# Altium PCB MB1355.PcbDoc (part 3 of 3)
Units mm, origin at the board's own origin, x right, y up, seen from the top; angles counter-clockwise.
Board outline 70.13 x 64.58 mm, 4 copper layers (L1, L2, L3, L4), stack 1.565 mm thick; 206 components, 160 nets, 707 pads, 1364 vias.
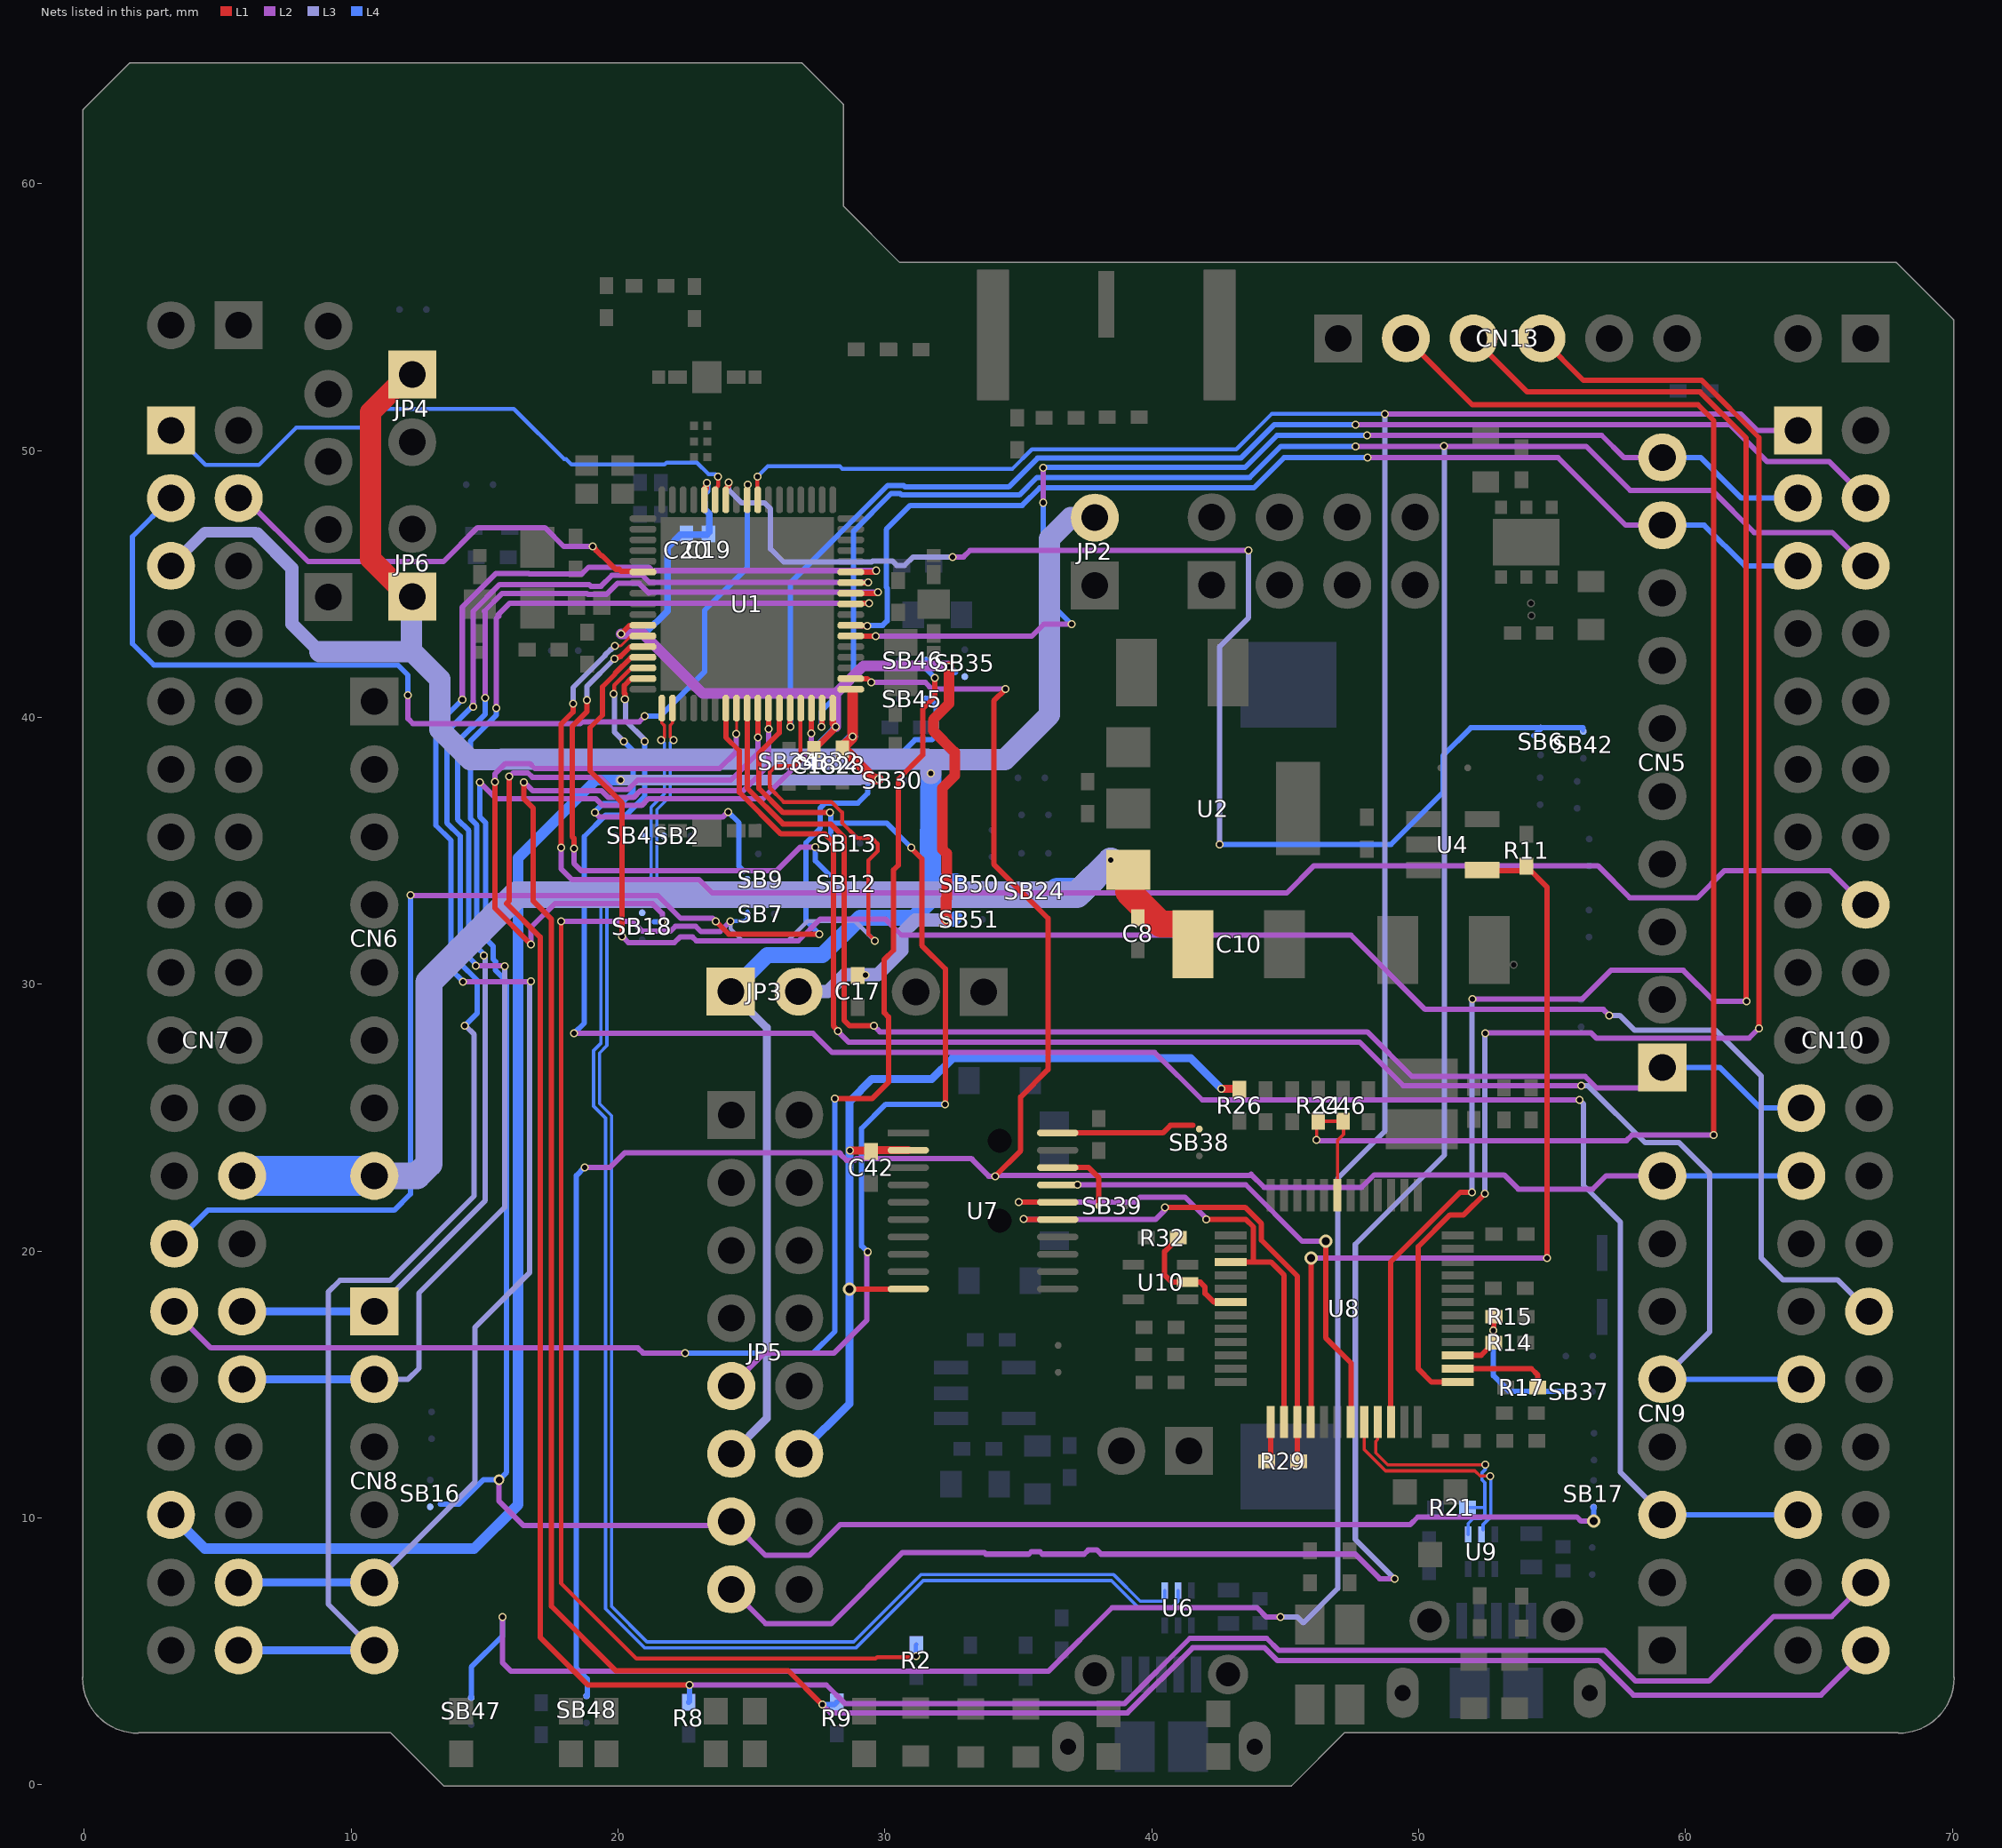
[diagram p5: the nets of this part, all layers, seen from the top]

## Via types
v1: diameter 0.3, hole 0.2, L1 to L4, tented both sides, 662 vias
v2: diameter 0.403, hole 0.2, L1 to L4, tented both sides, 628 vias
v3: diameter 0.4, hole 0.25, L1 to L4, tented both sides, 50 vias
v4: diameter 0.5, hole 0.3, L1 to L4, tented both sides, 24 vias

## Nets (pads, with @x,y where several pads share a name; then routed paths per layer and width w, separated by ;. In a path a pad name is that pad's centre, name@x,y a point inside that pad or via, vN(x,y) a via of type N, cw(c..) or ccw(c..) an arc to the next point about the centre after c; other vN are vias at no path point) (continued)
PB3: JP5.9 SB13.1 U1.63 | length 37.9
  L1 w0.2: U1.63@26.044,40.349 26.044,39.42 25.278,38.654 25.278,37.342 26.187,36.433 v1(27.939,36.434) ; v1(30.989,35.124) 30.989,35.104 31.385,34.708 31.385,31.456 32.263,30.578 32.263,25.522 v1(32.249,25.508)
  L2 w0.2: JP5.9@24.247,14.947 25.485,16.185 28.096,16.185 29.329,17.418 29.329,19.965 v1(29.36,19.965)
  L4 w0.2: v1(27.939,36.434) 27.939,36.421 27.97,36.39 27.97,36.043 ; 27.97,35.398 27.97,36.043 ; v1(29.36,19.965) 29.128,20.197 29.128,24.6 30.036,25.508 v1(32.249,25.508) ; v1(30.989,35.124) 30.07,36.043 27.97,36.043
PB4: CN10.4 U1.64 | length 50.1
  L1 w0.2: U1.64@26.444,40.349 26.444,39.658 v1(26.459,39.643)
  L2 w0.2: v1(47.628,50.968) 61.673,50.968 63.054,49.586 65.384,49.586 CN10.4@66.75,48.22
  L4 w0.2: v1(26.459,39.643) 26.459,45.033 26.453,45.039 30.103,48.689 30.702,48.689 30.756,48.636 34.637,48.636 35.719,49.718 43.338,49.718 44.593,50.973 44.598,50.968 v1(47.628,50.968)
PB5: R2.1 SB7.1 U1.65 | length 67
  L1 w0.15: v1(17.87,32.352) 17.87,7.544 20.687,4.727 29.644,4.727 29.707,4.79 31.168,4.79 v1(31.168,4.829) ; U1.65@26.844,40.349 26.838,40.343 26.838,38.372 26.736,38.269 26.725,38.269 26.625,38.17 25.901,38.17 25.685,37.954 25.685,37.36 26.209,36.836 27.996,36.836 28.392,36.44 28.392,36.053 28.968,35.477 29.512,35.477 29.63,35.36 29.63,35.358 29.729,35.259 29.729,34.989 29.389,34.649 29.389,31.876 v1(29.63,31.634)
  L2 w0.2: v1(17.87,32.352) 20.536,32.352 20.903,31.985 21.963,31.985 22.155,32.177 22.906,32.177 23.108,31.975 23.825,31.975 v1(24.214,32.364)
  L3 w0.15: v1(24.214,32.364) 24.214,32.086 24.664,31.636 26.37,31.636 27.098,32.365 28.886,32.365 29.63,31.62 v1(29.63,31.634)
  L4 w0.15: v1(17.87,32.352) v1@17.872,32.354 ; v1@24.214,32.384 v1(24.214,32.364) 24.737,32.364 24.847,32.474 SB7.1@24.847,32.739 ; v1(31.168,4.829) 31.168,5.256 R2.1@31.175,5.263
PB6: JP5.13 SB16.2 SB17.1 U1.66 | length 88.4
  L1 w0.2: v1(27.238,39.405) 27.238,40.343 U1.66@27.244,40.349
  L2 w0.2: v1(14.816,37.576) 15.436,36.956 19.165,36.956 19.424,36.697 20.885,36.697 21.144,36.956 25.439,36.956 27.244,38.761 27.238,38.767 v1(27.238,39.405) 27.238,39.451 v1@27.23,39.459 ; v3(15.546,11.427) 15.546,10.632 16.452,9.726 24.399,9.726 25.529,8.596 27.166,8.596 28.327,9.757 49.69,9.757 49.967,10.034 55.933,10.034 56.089,9.878 v4(56.556,9.878)
  L4 w0.2: 13.35,10.515 14.04,10.515 14.952,11.427 v3(15.546,11.427) ; v1(14.816,37.576) 14.816,36.285 15.048,36.053 15.048,31.7 15.326,31.422 15.326,31.228 15.326,30.937 15.421,30.842 15.401,30.822 15.401,30.532 15.825,30.108 15.825,11.71 v3@15.544,11.429 ; v4(56.556,9.878) SB17.1@56.556,10.405
PB7: CN10.6 JP5.15 U1.67 | length 121.2
  L1 w0.2: v1(27.621,39.652) 27.644,39.675 U1.67@27.644,40.349
  L2 w0.2: JP5.15@24.247,7.327 25.535,6.039 27.995,6.039 30.653,8.697 33.74,8.697 33.792,8.645 35.391,8.645 35.481,8.736 35.813,8.736 35.903,8.645 37.463,8.645 37.618,8.8 37.949,8.8 38.104,8.645 47.623,8.645 48.539,7.729 v1(49.095,7.729) ; v1(47.635,50.159) 56.275,50.159 57.923,48.511 60.99,48.511 62.569,46.932 65.498,46.932 CN10.6@66.75,45.68
  L3 w0.2: v1(49.095,7.729) 47.627,9.197 47.627,20.257 50.965,23.595 50.965,50.166 v1(50.955,50.176)
  L4 w0.2: v1(27.621,39.652) 27.621,40.234 28.826,41.439 28.826,46.98 30.235,48.389 30.578,48.389 30.631,48.336 35.039,48.336 35.692,48.989 43.667,48.989 44.837,50.159 v1(47.635,50.159)
PB8: CN5.10 CN10.3 U1.6 | length 44.5
  L1 w0.2: U1.6@28.722,43.052 29.657,43.052 v1(29.663,43.046)
  L2 w0.2: v1(29.663,43.046) 35.506,43.046 35.956,43.496 v1(36.992,43.496) ; v1@35.925,49.364 35.925,48.095 35.93,48.09 v1(35.93,48.049) ; v1(48.062,50.564) 56.851,50.564 56.857,50.57 57.683,49.744 CN5.10@59.13,49.744
  L4 w0.2: v1@35.925,49.368 43.491,49.368 44.693,50.57 44.699,50.564 v1(48.062,50.564) ; v1(35.93,48.049) 35.93,44.558 v1(36.992,43.496) ; CN5.10@59.13,49.744 60.565,49.744 62.089,48.22 CN10.3@64.21,48.22
  other v1: 35.927,49.36
PB9: CN5.9 CN10.5 U1.7 | length 41.9
  L1 w0.2: U1.7@28.722,43.452 28.728,43.458 28.749,43.437 v1(29.34,43.437)
  L2 w0.2: v1(48.077,49.74) 55.222,49.74 57.758,47.204 CN5.9@59.13,47.204
  L4 w0.2: v1(29.34,43.437) 29.35,43.448 29.919,43.448 30.087,43.616 30.087,44.842 30.048,44.881 30.048,47.047 30.949,47.948 35.146,47.948 35.803,48.605 43.825,48.605 44.96,49.74 v1(48.077,49.74) ; CN5.9@59.13,47.204 60.696,47.204 62.22,45.68 CN10.5@64.21,45.68
PB10: SB6.2 SB42.1 U1.28 | length 51.1
  L1 w0.2: U1.28@24.044,48.155 24.044,48.573 24.119,48.648 v1@24.119,48.676 ; v1(24.152,48.809) 24.152,48.715 24.155,48.712 v1@24.135,48.692 ; v1@24.119,48.676 24.119,48.692 v1@24.135,48.692 ; v1@24.119,48.676 v1@24.135,48.692
  L2 w0.2: v1(32.543,46.016) 32.948,46.016 33.184,46.252 v1(43.628,46.252)
  L3 w0.2: v1(24.152,48.809) 24.152,48.522 24.627,48.047 25.485,48.047 25.716,47.817 25.716,46.314 26.209,45.82 29.502,45.82 29.534,45.852 30.291,45.852 30.447,45.696 30.737,45.696 31.057,46.016 v1(32.543,46.016) ; v1(42.546,35.247) 42.546,42.659 43.628,43.741 v1(43.628,46.252)
  L4 w0.127: SB6.2@54.57,39.602 54.578,39.61 SB6.2@54.58,39.612 ; SB42.1@56.155,39.496 56.155,39.612
  L4 w0.2: v1(42.546,35.247) 48.968,35.247 50.907,37.186 50.907,38.567 51.95,39.61 54.578,39.61 54.606,39.61 54.314,39.318 ; SB6.2@54.58,39.612 56.155,39.612
PB11: CN7.1 U1.29 | length 23.4
  L1 w0.15: 23.717,48.654 23.752,48.689 v1(23.752,49.024)
  L4 w0.15: CN7.1@3.25,50.76 4.544,49.466 6.548,49.466 7.938,50.856 10.412,50.856 11.117,51.561 16.1,51.561 17.985,49.676 18.055,49.676 18.255,49.476 21.746,49.476 21.822,49.552 22.96,49.552 23.39,49.122 23.654,49.122 v1(23.752,49.024) 23.752,49.014 v1@23.733,48.995
PB12: CN10.16 U1.46 | length 61.5
  L1 w0.1: v1(19.88,42.678) 20.106,42.678 20.48,43.052 U1.46@20.941,43.052
  L1 w0.2: v1(17.87,35.119) 17.87,39.757 18.32,40.207 v1(18.32,40.516)
  L2 w0.2: v1@17.877,35.102 17.877,34.316 18.262,33.931 23.025,33.931 23.536,33.42 45.055,33.42 46.077,34.442 56.713,34.442 57.912,33.243 60.441,33.243 61.459,34.261 65.398,34.261 66.679,32.98 CN10.16@66.75,32.98
  L3 w0.2: v1(18.32,40.516) 18.32,41.118 19.516,42.314 19.516,42.341 19.721,42.546 19.748,42.546 v1(19.88,42.678)
PB13: SB12.1 U1.47 | length 21
  L1 w0.1: 20.076,42.29 20.032,42.315 20.468,42.682 U1.47@20.468,42.652
  L1 w0.2: v1(18.346,35.096) 18.346,35.47 18.282,35.534 18.282,39.66 18.831,40.209 v1(18.831,40.643) ; v1(19.866,42.196) 20.097,42.281 20.468,42.652 U1.47@20.941,42.652
  L2 w0.2: v1(18.346,35.096) 18.346,34.535 18.617,34.264 25.952,34.264 26.821,35.133 v1(27.391,35.133)
  L3 w0.2: v1(18.831,40.643) 18.831,41.161 v1(19.866,42.196)
  L4 w0.2: v1(27.391,35.133) 27.391,34.629 27.912,34.108
PB14: CN10.28 U1.48 | length 69.4
  L1 w0.15: U1.48@20.483,42.252 U1.48@20.941,42.252
  L1 w0.17: 19.418,41.15 19.897,41.629 19.897,41.657
  L1 w0.2: 19.418,41.15 19.418,40.085 18.952,39.619 18.952,37.999 20.154,36.797 v1(20.154,31.796) ; 19.897,41.657 U1.48@20.483,42.242
  L2 w0.2: v1(20.154,31.796) 20.389,31.561 22.112,31.561 22.324,31.773 22.791,31.773 22.938,31.626 26.761,31.626 27.583,32.448 30.017,32.448 30.622,31.843 47.463,31.843 50.247,29.059 56.92,29.059 v1(57.148,28.831)
  L3 w0.2: v1(57.148,28.831) 57.155,28.838 57.53,28.838 58.084,28.284 61.113,28.284 62.827,26.57 62.827,19.746 63.644,18.929 65.688,18.929 CN10.28@66.877,17.74
PB15: SB9.1 U1.49 | length 15.1
  L1 w0.15: v1@19.863,40.906 19.863,41.208 20.507,41.852 U1.49@20.941,41.852
  L2 w0.2: v1(19.138,36.44) 19.313,36.265 23.925,36.265 24.151,36.491 24.151,36.484 v1(24.126,36.459)
  L3 w0.2: v1@19.863,40.906 19.863,39.453 v1(20.21,39.106)
  L4 w0.2: v1(19.138,36.44) 19.132,36.446 19.132,36.458 19.447,36.773 20.132,36.773 20.569,37.21 20.569,38.747 v1(20.21,39.106) ; v1(24.126,36.459) 24.531,36.054 24.531,34.422 24.72,34.233
  other v1: 19.836,40.884
PC0: CN7.28 CN8.1 U1.9 | length 48.3
  L1 w0.2: U1.9@28.722,44.252 28.804,44.252 28.823,44.271 v1(29.407,44.271)
  L2 w0.2: v1(15.432,40.352) 15.432,43.699 15.536,43.802 15.499,43.839 15.931,44.271 v1(29.407,44.271)
  L3 w0.2: CN8.1@10.87,17.74 15.029,21.899 15.029,31.072 15.019,31.082 v1(14.976,31.082)
  L4 w0.2: v1(14.976,31.082) 15.023,31.082 14.714,31.391 14.714,35.963 14.466,36.211 14.466,39.112 15.432,40.078 v1(15.432,40.352)
  L4 w0.3: CN7.28@5.917,17.74 CN8.1@10.87,17.74
PC1: CN7.30 CN8.2 U1.10 | length 54.7
  L1 w0.2: U1.10@28.722,44.652 29.692,44.652 v1(29.737,44.697)
  L2 w0.2: v1(14.679,30.69) 15.738,30.69 v1(15.751,30.677) ; v1(15.016,40.734) 15.016,43.955 14.991,43.98 15.652,44.641 18.838,44.641 18.862,44.616 19.576,44.616 19.98,45.02 20.793,45.02 21.157,44.656 21.199,44.697 v1(29.737,44.697)
  L3 w0.2: CN8.2@10.87,15.2 12.134,15.2 12.542,15.608 12.542,18.429 15.751,21.638 v1(15.751,30.677)
  L4 w0.2: v1(14.679,30.69) 14.679,30.744 14.414,31.009 14.414,35.758 13.988,36.184 13.988,39.087 15.016,40.115 v1(15.016,40.734)
  L4 w0.3: CN7.30@5.917,15.2 CN8.2@10.87,15.2
PC2: CN7.38 CN8.6 U1.11 | length 65.6
  L1 w0.2: U1.11@28.722,45.052 v1@29.365,45.052
  L2 w0.2: v1(14.566,40.398) 14.566,43.979 15.571,44.983 18.919,44.983 18.987,44.916 19.364,44.916 19.767,45.32 20.918,45.32 21.182,45.056 23.417,45.056 ; 23.417,45.056 24.204,45.056 24.211,45.063 v1(29.365,45.063)
  L3 w0.2: CN8.6@10.87,5.04 9.139,6.771 9.139,18.467 9.578,18.906 11.448,18.906 14.613,22.071 14.613,28.116 v1@14.275,28.454
  L4 w0.2: v1(14.263,28.454) 14.73,28.921 14.73,30.144 14.084,30.79 14.084,35.557 13.589,36.052 13.589,39.458 v1@14.516,40.385 ; v1(14.566,40.398) 14.566,40.599
  L4 w0.3: CN7.38@5.79,5.04 CN8.6@10.87,5.04
PC3: CN7.36 CN8.5 U1.12 | length 64.7
  L1 w0.2: U1.12@28.722,45.452 29.618,45.452 v1@29.668,45.502
  L2 w0.2: v1(14.166,40.667) 14.166,44.134 15.421,45.389 16.658,45.389 16.672,45.376 18.644,45.376 18.901,45.632 21.152,45.632 21.33,45.454 21.379,45.502 v1(29.679,45.502) ; v1(14.194,30.103) 16.722,30.103 v1(16.733,30.114)
  L3 w0.2: CN8.5@10.87,7.58 14.637,11.347 14.637,17.14 16.681,19.184 16.681,30.062 v1(16.733,30.114)
  L4 w0.2: v1(14.166,40.667) 13.177,39.678 13.177,35.955 13.741,35.391 13.741,30.556 v1(14.194,30.103)
  L4 w0.3: CN7.36@5.79,7.58 CN8.5@10.87,7.58
PC4: CN10.1 SB47.2 U1.25 | length 124.3
  L1 w0.15: U1.25@25.21,48.189 25.21,48.557 25.226,48.557 25.226,48.996 v1@25.21,49.012
  L2 w0.2: v1(15.668,6.291) 15.668,4.578 15.983,4.263 36.136,4.263 38.511,6.638 43.944,6.638 44.294,6.288 v1(44.814,6.288) ; v1(48.729,51.363) 62.076,51.363 62.679,50.76 CN10.1@64.21,50.76
  L3 w0.2: v1(44.814,6.288) 45.457,6.288 45.679,6.066 46.971,7.358 46.971,22.728 48.727,24.484 48.727,51.361 v1(48.729,51.363)
  L4 w0.15: v1@25.21,49.012 25.611,49.413 28.308,49.413 28.4,49.321 34.781,49.321 35.509,50.049 43.168,50.049 44.49,51.371 48.721,51.371 v1(48.729,51.363)
  L4 w0.2: SB47.2@14.505,3.267 14.505,4.411 15.668,5.574 v1(15.668,6.291)
  other v1: 25.225,49.026
PC5: CN7.3 U1.26 | length 38.2
  L2 w0.2: v1(12.131,40.827) 12.131,39.954 12.311,39.774 18.592,39.774 18.659,39.842 20.802,39.842 v1(21.006,40.046)
  L4 w0.2: CN7.3@3.25,48.22 1.807,46.777 1.807,42.763 2.607,41.963 11.751,41.963 12.131,41.583 v1(12.131,40.827) ; v1(21.006,40.046) 21.574,40.046 23.24,41.712 23.24,44.012 24.851,45.623 v1@24.851,48.728
  other v1: 24.856,48.719
PC6: CN9.3 CN10.33 U1.50 | length 76.3
  L1 w0.2: v1@20.277,40.704 20.265,40.736 20.265,40.882 20.241,40.907 20.241,41.197 20.496,41.452 U1.50@20.941,41.452
  L2 w0.2: v1(18.349,28.159) 27.31,28.159 28.024,27.445 40.112,27.445 41.891,25.666 v1(56.027,25.666)
  L3 w0.2: v1@20.277,40.704 20.277,39.883 21.002,39.158 v1(21.002,39.106) ; v1(56.027,25.666) 56.174,25.519 56.174,22.47 57.563,21.081 57.563,11.711 59.13,10.144 CN9.3@59.13,10.12
  L4 w0.2: v1(18.349,28.159) 18.735,28.545 18.735,35.54 19.527,36.332 20.293,36.332 21.002,37.041 v1(21.002,39.106) ; CN9.3@59.13,10.12 CN10.33@64.21,10.12
  other v1: 20.259,40.68
PC10: CN9.5 CN10.29 U1.58 | length 63.3
  L1 w0.2: U1.58@24.044,40.349 24.044,39.253 24.544,38.753 24.544,37.195 26.103,35.636 27.752,35.636 28.067,35.321 28.067,28.44 v1@28.252,28.255
  L2 w0.2: v1(28.248,28.255) 28.248,28.222 28.637,27.833 47.785,27.833 49.42,26.198 v1(56.096,26.196)
  L3 w0.2: v1(56.096,26.196) 56.355,26.196 58.488,24.063 59.762,24.063 60.9,22.925 60.9,16.97 CN9.5@59.13,15.2
  L4 w0.2: CN9.5@59.13,15.2 CN10.29@64.337,15.2
PC11: SB18.2 U1.59 | length 24.9
  L1 w0.1: v1(24.435,39.387) 24.444,39.396 U1.59@24.444,40.349
  L1 w0.2: v1(15.389,37.592) 15.389,32.852 16.733,31.508 v1(16.733,31.489)
  L2 w0.2: v1(15.389,37.592) 15.385,37.596 15.385,37.88 15.779,38.274 16.698,38.274 16.886,38.086 23.805,38.086 24.435,38.716 v1(24.435,39.387) ; v1(16.733,31.489) 16.733,32.124 17.631,33.022 21.292,33.022 21.658,32.656 21.658,32.335 v1(21.653,32.335)
  L4 w0.2: 21.351,32.348 21.364,32.335 v1(21.653,32.335)
PC12: CN5.1 CN10.21 U1.60 | length 52.1
  L1 w0.2: U1.60@24.844,40.349 24.844,37.346 26.183,36.007 27.973,36.007 28.472,35.508 28.472,28.652 28.68,28.444 v1(29.591,28.444)
  L2 w0.2: v1(29.591,28.444) 29.813,28.222 48.075,28.222 49.751,26.546 56.241,26.546 56.674,26.113 58.359,26.113 CN5.1@59.13,26.884
  L4 w0.2: CN5.1@59.13,26.884 61.28,26.884 62.804,25.36 CN10.21@64.337,25.36
PC13: CN9.8 CN10.23 SB48.2 U1.2 | length 93.3
  L1 w0.2: U1.2@28.722,41.452 29.34,41.452 v1(29.483,41.309) ; v1(34.136,22.812) 35.086,23.762 35.086,25.78 36.109,26.803 36.109,32.475 34.08,34.504 34.08,40.619 v1(34.524,41.063)
  L2 w0.2: v1(18.75,23.139) 19.706,23.139 20.247,23.68 28.304,23.68 28.336,23.648 28.336,23.631 28.564,23.403 28.854,23.403 28.928,23.477 33.239,23.477 33.287,23.429 33.287,23.414 33.89,22.812 v1(34.136,22.812) 34.16,22.836 43.677,22.836 43.721,22.88 44.212,22.389 47.865,22.389 48.335,22.859 53.201,22.859 53.733,22.327 56.525,22.327 57.018,22.82 CN9.8@59.13,22.82 ; v1(29.483,41.309) 31.52,41.309 31.766,41.063 v1(34.524,41.063)
  L4 w0.2: v1(18.75,23.139) 18.442,22.832 18.442,4.376 18.845,3.973 18.845,3.355 SB48.2@18.821,3.331 ; CN9.8@59.13,22.82 CN10.23@64.337,22.82
PC14: CN7.25 SB45.2 | length 49.7
  L1 w0.2: v1(23.664,32.363) 24.145,31.882 v1(27.54,31.882) v1@27.571,31.882
  L2 w0.2: v1(12.226,33.339) 12.243,33.322 21.499,33.322 22.344,32.477 23.55,32.477 v1(23.664,32.363)
  L4 w0.2: CN7.25@3.377,20.28 4.631,21.534 11.614,21.534 12.226,22.145 v1(12.226,33.339) ; v1(27.54,31.882) 27.041,32.381 27.041,35.306 27.583,35.848 27.583,36.608 27.764,36.789 28.985,36.789 29.351,37.155 29.351,38.25 29.593,38.492 30.459,38.492 31.129,39.162 31.767,39.162 31.913,39.308 31.913,40.483 31.698,40.698 SB45.2@31.533,40.698
PC15: CN7.27 SB46.2 | length 53.5
  L1 w0.2: v1(28.123,25.72) 29.528,25.72 30.136,26.328 30.136,28.778 29.977,28.937 29.977,30.932 30.324,31.278 30.324,34.282 30.504,34.463 30.504,37.686 31.413,38.595 31.413,40.088 31.416,40.091 31.416,40.323 31.872,40.779 v1(31.872,41.484)
  L2 w0.2: CN7.27@3.377,17.74 4.744,16.373 20.744,16.373 20.936,16.181 v1(22.516,16.181)
  L4 w0.2: v1(22.516,16.181) 27.315,16.181 28.124,16.99 28.124,25.719 v1(28.123,25.72) ; SB46.2@31.543,42.147 31.543,41.813 v1(31.872,41.484)
PD0: CN10.36 R8.2 U1.61 | length 99.3
  L1 w0.2: v1(15.925,37.792) 15.925,33.133 15.822,33.031 17.084,31.769 17.084,5.529 18.864,3.749 22.674,3.749 v1(22.681,3.742) ; U1.61@25.244,40.349 25.244,39.257 v1(25.246,39.259)
  L2 w0.2: v1(15.925,37.792) 15.925,37.778 16.073,37.926 16.622,37.926 16.79,37.758 19.326,37.758 19.787,37.297 20.378,37.297 20.732,37.651 24.231,37.651 25.246,38.666 v1(25.246,39.259) ; v1@22.673,3.742 v1(22.681,3.742) 27.808,3.742 28.5,3.05 38.986,3.05 41.425,5.489 44.307,5.489 44.75,5.046 56.97,5.046 58.126,3.89 60.876,3.89 63.293,6.307 65.477,6.307 CN10.36@66.75,7.58
  L4 w0.2: R8.2@22.646,3.095 22.681,3.13 v1(22.681,3.742)
PD1: CN10.38 R9.2 U1.62 | length 97.3
  L1 w0.2: v1(16.477,37.576) 16.477,36.947 16.825,36.599 16.825,33.118 17.508,32.435 17.508,6.69 19.915,4.283 26.377,4.283 v1(27.652,3.008) ; U1.62@25.644,40.349 25.644,39.572 v1(25.645,39.571)
  L2 w0.2: v1(16.477,37.576) 16.797,37.256 19.38,37.256 19.639,36.997 20.589,36.997 20.848,37.256 24.7,37.256 25.645,38.201 v1(25.645,39.571) ; v1(27.652,3.008) 27.964,2.696 39.093,2.696 41.532,5.135 44.227,5.135 44.702,4.66 56.749,4.66 58.043,3.366 65.076,3.366 CN10.38@66.75,5.04
  L4 w0.2: v1(27.652,3.008) 28.108,3.008 R9.2@28.203,3.103
PE4: CN7.4 U1.40 | length 17.4
  L1 w0.2: v1(19.054,46.413) 19.176,46.291 19.176,46.263 19.381,46.058 19.409,46.058 19.915,45.552 20.043,45.552 20.111,45.484 20.909,45.484 U1.40@20.941,45.452
  L2 w0.2: CN7.4@5.79,48.22 6.015,48.22 8.392,45.843 13.465,45.843 14.737,47.115 17.257,47.115 17.964,46.408 17.969,46.413 v1(19.054,46.413)
PWR_ENN: R11.2 U4.4 U8.28 | length 31.6
  L1 w0.2: U8.28@45.96,13.596 45.975,13.611 v4(45.975,19.733) ; U4.4@52.523,34.265 53.877,34.265 R11.2@54.034,34.422 54.818,33.638 54.818,19.749 v1(54.811,19.742)
  L2 w0.2: v4(45.975,19.733) 45.979,19.729 45.992,19.742 v1(54.811,19.742)
PWR_EXT: R14.2 R15.1 SB37.2 U8.39 | length 7.2
  L1 w0.2: U8.39@51.46,16.096 52.341,16.096 R14.2@52.811,16.566 52.811,17.536 R15.1@52.821,17.546
  L4 w0.2: v1(52.802,17.035) 52.802,15.337 53.4,14.739 SB37.2@55.503,14.739
STLK_RST: C46.2 CN13.2 R24.1 U8.7 | length 59.1
  L1 w0.127: v1(46.178,24.166) 46.178,24.805 R24.1@46.24,24.867 C46.2@47.17,24.867 47.19,24.847 47.19,24.377 46.96,24.147 U8.7@46.96,22.096
  L1 w0.2: CN13.2@49.52,54.204 52.012,51.712 60.47,51.712 61.054,51.128 61.054,24.355 v1(61.058,24.351)
  L2 w0.2: v1(46.178,24.166) 46.202,24.142 57.783,24.142 57.992,24.351 v1(61.058,24.351)
STLK_RX: SB39.1 U7.18 | length 2.8
  L1 w0.2: U7.18@36.475,23.131 37.637,23.131 38.01,22.758 SB39.1@38.01,21.696
STLK_SWCLK: CN13.4 U8.37 | length 57.9
  L1 w0.2: U8.37@51.46,15.096 50.48,15.096 49.987,15.589 49.987,20.173 51.175,21.361 51.688,21.361 v1(52.482,22.155) ; CN13.4@54.6,54.204 56.176,52.628 60.611,52.628 62.75,50.489 v1(62.75,28.354)
  L2 w0.2: v1(52.496,28.166) 52.513,28.183 56.456,28.183 56.652,27.987 62.383,27.987 v1(62.75,28.354)
  L3 w0.2: v1(52.482,22.155) 52.482,28.162 52.502,28.162 52.506,28.166 v1(52.496,28.166)
STLK_SWDIO: CN13.3 U8.34 | length 61.5
  L1 w0.2: U8.34@48.96,13.596 48.95,13.606 48.95,19.598 51.556,22.204 v1(52.001,22.204) ; CN13.3@52.06,54.204 54.068,52.196 60.551,52.196 62.275,50.472 v1@62.275,29.351
  L2 w0.2: v1(52.021,29.452) 56.13,29.452 57.202,30.524 59.917,30.524 61.079,29.362 v1(62.28,29.362)
  L3 w0.2: v1(52.001,22.204) 52.001,29.432 v1(52.021,29.452)
STLK_TX: SB38.1 U7.20 | length 5.2
  L1 w0.2: U7.20@36.475,24.431 40.417,24.431 40.7,24.714 41.547,24.714
T_NRST: R32.1 U8.18 U10.2 | length 4.7
  L1 w0.2: R32.1@40.999,20.506 40.48,19.987 40.48,19.106 40.75,18.836 U10.2@41.346,18.836 41.82,18.836 42,18.656 42,18.416 42.32,18.096 U8.18@42.96,18.096
T_SWCLK: U7.16 U8.15 U8.26 | length 19.8
  L1 w0.2: v1(35.017,21.834) 35.146,21.834 v1@35.146,21.841 ; v1@35.149,21.831 U7.16@36.475,21.831 ; v1(42.034,21.196) 43.521,21.196 43.811,20.906 43.811,19.596 ; U8.15@42.96,19.596 44.46,19.596 44.96,19.096 U8.26@44.96,13.596
  L2 w0.2: v1(35.017,21.834) 39.368,21.834 39.562,22.028 41.244,22.028 42.034,21.238 v1(42.034,21.196)
T_SWDIO: R29.1 U7.15 U8.27 | length 20.1
  L1 w0.2: v1(35.207,21.199) 35.225,21.181 U7.15@36.475,21.181 ; v1(40.501,21.645) 43.496,21.645 44.111,21.03 44.111,20.407 45.46,19.058 U8.27@45.46,13.596 R29.1@45.46,12.175
  L2 w0.2: v1@35.207,21.195 40.151,21.195 40.501,21.545 v1(40.501,21.645)
T_SWDIO_IN: R29.2 U8.25 | length 1.5
  L1 w0.2: R29.2@44.311,12.126 44.46,12.275 U8.25@44.46,13.596
T_SWO: U7.17 U8.31 | length 18.1
  L1 w0.2: U7.17@36.475,22.481 36.48,22.486 v1(37.214,22.486) ; v4(46.514,20.37) 46.514,16.758 47.47,15.802 47.47,13.606 U8.31@47.46,13.596
  L2 w0.2: v1(37.214,22.486) 43.522,22.486 45.638,20.37 v4(46.514,20.37)
T_VDD: C42.2 JP5.12 R26.2 U7.2 U7.10 | length 34.1
  L1 w0.2: v4@28.68,18.581 U7.10@30.875,18.581
  L1 w0.3: v1(28.686,23.776) 29.432,23.776 C42.2@29.478,23.73 29.529,23.781 U7.2@30.875,23.781 ; v1(42.601,26.088) 43.257,26.088 R26.2@43.28,26.065
  L4 w0.3: JP5.12@26.859,12.467 28.68,14.288 v4(28.68,18.577) 28.68,25.612 29.519,26.451 31.762,26.451 32.538,27.227 41.462,27.227 v1(42.601,26.088)
USB_N: SB4.1 U1.52 U6.2 | length 59.7
  L1 w0.12: v1(21.613,39.147) 21.643,39.147 21.734,39.238 21.734,39.699 21.644,39.789 U1.52@21.644,40.349
  L4 w0.12: v1(21.613,39.147) 21.637,39.147 21.737,39.047 21.737,37.134 21.237,36.634 21.237,34.035 20.552,33.349 19.682,33.349 19.366,33.034 19.366,27.795 19.087,27.516 19.087,25.435 19.536,24.986 19.536,6.597 20.994,5.138 28.923,5.138 31.438,7.653 38.486,7.653 39.477,6.662 40.773,6.662 40.986,6.875 U6.2@40.986,7.28
USB_P: SB2.1 U1.53 U6.1 | length 58.7
  L1 w0.12: U1.53@22.044,40.349 22.044,39.789 21.954,39.699 21.954,39.259 22.066,39.147 v1(22.081,39.147)
  L4 w0.12: v1(22.081,39.147) 22.042,39.147 21.957,39.062 21.957,37.043 21.457,36.543 21.457,33.944 20.643,33.129 19.773,33.129 19.586,32.943 19.586,27.704 19.307,27.425 19.307,25.526 19.756,25.077 19.756,6.688 21.085,5.358 28.832,5.358 31.347,7.873 38.577,7.873 39.568,6.882 40.421,6.882 40.486,6.946 U6.1@40.486,7.28
USB_RENUMN: R17.2 U8.38 | length 3.6
  L1 w0.2: U8.38@51.46,15.596 54.228,15.596 54.455,15.369 R17.2@54.455,14.889
USBSTLK_N: U8.32 U9.2 | length 8.3
  L1 w0.12: U8.32@47.96,13.596 47.96,12.564 48.756,11.768 52.105,11.768 52.301,11.571 v1(52.687,11.571)
  L4 w0.12: U9.2@52.415,9.563 52.415,9.751 52.701,10.037 52.701,11.546 v1@52.726,11.571 ; v1(52.687,11.571) v1@52.726,11.571 ; v1@52.727,11.573 v1@52.726,11.571
USBSTLK_P: R21.1 U8.33 U9.1 | length 9.3
  L1 w0.12: U8.33@48.46,13.596 48.46,12.936 48.39,12.866 48.39,12.445 48.847,11.988 52.485,11.988 v1(52.496,11.999)
  L4 w0.12: R21.1@51.831,10.389 52.475,10.389 52.481,10.395 52.481,11.325 52.377,11.429 52.377,11.7 52.496,11.818 v1(52.496,11.999) ; U9.1@51.852,9.386 51.852,9.794 52.039,9.982 52.334,9.982 52.481,10.128 52.481,10.389
VBAT: C28.1 CN7.33 SB30.2 SB32.1 U1.1 | length 58.4
  L1 w0.4: 28.795,40.873 28.795,39.251 28.41,38.866 29.596,37.68 v1(29.751,37.68)
  L3 w0.4: CN7.33@2.949,10.12 CN7.33@3.25,10.12 ; v1(20.108,37.647) 29.053,37.647 ; 29.162,37.68 v1(29.751,37.68)
  L4 w0.4: CN7.33@3.25,10.12 4.524,8.846 14.6,8.846 16.253,10.499 16.253,34.734 19.166,37.647 v1(20.108,37.647) ; SB32.1@28.396,38.358 28.396,38.89 v1(28.786,39.28)
VDD: CN7.5 JP2.2 JP3.1 JP4.1 JP5.11 JP6.1 SB50.1 | length 94.2
  L1 w0.8: JP6.1@12.163,44.509 10.73,45.942 10.73,51.435 JP4.1@12.192,52.897
  L3 w0.3: JP3.1@24.222,29.723 25.571,28.374 25.571,13.731 JP5.11@24.247,12.407
  L3 w0.4: CN7.5@3.25,45.68 4.52,46.95 6.422,46.95 6.492,46.88
  L3 w0.5: 6.492,46.88 7.784,45.588 7.784,43.503 8.823,42.464
  L3 w0.8: 8.823,42.464 12.242,42.464 ; JP6.1@11.983,44.422 12.255,44.15 12.255,42.492 13.321,41.426 13.321,39.546 14.453,38.414 15.627,38.414 15.656,38.442 31.594,38.442 31.622,38.414 ; v1(31.721,37.898) 31.721,38.315 31.622,38.414 ; JP2.2@38.046,47.307 JP2.2@37.867,47.486 37.863,47.49 36.964,47.49 36.171,46.697 36.171,40.093 34.492,38.414 31.622,38.414
  L4 w0.6: JP3.1@24.222,29.723 25.589,31.09 27.663,31.09 29.07,32.497 31.087,32.497 31.697,33.107 31.697,33.753 31.697,33.761
  L4 w0.8: 31.697,33.753 31.697,33.761 ; v1(31.721,37.898) 31.697,33.761 ; SB50.1@32.66,33.761 31.697,33.761
VDD_MCU: C17.1 C18.1 C19.1 C20.1 JP3.2 SB32.2 SB34.2 SB35.2 SB51.1 U1.30 U1.45 U1.68 | length 46.3
  L1 w0.2: v1(20.112,43.131) 20.433,43.452 U1.45@20.941,43.452
  L1 w0.25: U1.30@23.244,48.155 23.244,48.54 23.294,48.59 U1.30@23.294,48.619 ; C18.1@27.344,38.802 v1@28.176,39.634 ; U1.68@28.044,40.349 28.044,39.766 v1(28.166,39.644)
  L1 w0.4: v1@32.326,32.41 32.295,32.441 32.295,33.215 32.313,33.233 32.313,34.903 32.161,35.055 32.161,37.357 32.616,37.812 32.616,38.699 31.813,39.502 31.813,39.922 32.411,40.52 v1(32.411,41.893)
  L2 w0.4: v1(20.112,43.131) 20.942,43.131 23.174,40.899 28.166,40.899 ; v1(28.166,39.644) 28.166,40.899 ; v1(32.411,41.893) 32.37,41.934 29.201,41.934 28.166,40.899
  L3 w0.5: JP3.2@26.762,29.723 27.862,29.723 28.497,30.358 29.732,30.358 30.633,31.259 30.633,31.889 31.154,32.41 v1(32.301,32.41) v1@32.311,32.41
  L4 w0.25: v1(20.112,43.131) 20.991,43.131 21.853,43.993 21.853,46.36 22.343,46.85 C19.1@23.333,46.85 ; v1(23.329,48.788) 23.346,48.771 23.346,48.486 23.245,48.384 23.245,47.811 23.423,47.633 C19.1@23.423,46.946 ; SB34.2@26.892,38.352 27.382,38.352 SB32.2@27.388,38.358 ; 27.45,38.668 27.45,38.928 v1(28.166,39.644) ; v1(32.411,41.893) 32.595,41.709 32.626,41.709
  L4 w0.5: v1(32.301,32.41) 32.571,32.41 SB51.1@32.67,32.509
  other v1: 29.269,30.348
VIN: C8.1 C10.1 CN6.8 CN7.24 SB24.2 U2.3 | length 47.3
  L1 w1: U2.3@38.845,34.004 U2.3@39.125,34.284 39.125,33.469 40.34,32.254 C10.1@40.796,32.254
  L3 w1: CN6.8@10.87,22.82 12.468,22.82 12.917,23.269 12.917,30.085 16.186,33.354 37.194,33.354 v1@38.464,34.624
  L4 w1: 36.459,33.495 37.335,33.495 v1@38.464,34.624
  L4 w1.5: CN7.24@5.917,22.82 CN6.8@10.87,22.82
  other v1: 38.464,34.649
pads on no net: CN6.1 CN7.9 CN7.11 CN7.17 CN7.21 CN7.22 CN7.23 CN7.26 CN7.29 CN7.31 CN7.35 CN7.37 CN10.2 CN10.10 CN10.18 CN13.5 SW5.NPTH1 SW5.NPTH2 U3.3 U3.5 U6.4 U7.7 U7.8 U7.9 U8.4 U8.11 U8.14 U8.16 U8.17 U8.19 U8.22 U8.29 U8.40 U8.41 U8.42 U8.43 U8.45 U8.46 U9.4 U10.1

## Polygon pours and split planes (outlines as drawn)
GND on L1 "GND_L01_P018" (solid, remove dead copper, pour order 18): -1.565,56.987 73.005,56.987 73.005,-6.573 -4.395,-6.573 -4.395,-6.253 -4.395,56.963 -1.015,56.963
NetR5_1 on L1 "NETR5_1_L01_P031" (solid, pour order 31): 22.994,50.975 cw(c23.241,50.975) 23.067,51.15 23.107,51.189 22.678,51.611 ccw(c22.924,51.365) 22.577,51.365 ccw(c22.848,51.365) 22.656,51.173 22.68,51.15 cw(c22.636,51.106) 22.698,51.106 22.698,50.754 22.994,50.754
ANT on L1 "L2-No Net" (solid, pour order 14): 19.778,57.015 19.778,58.64 17.303,58.64 17.303,59.365 26.228,59.365 26.228,61.015 17.303,61.015 17.303,61.74 26.253,61.74 26.253,63.415 19.278,63.415 19.278,62.965 23.678,62.965 25.778,62.965 25.778,62.215 16.853,62.215 16.853,62.165 16.853,60.54 16.878,60.54 25.753,60.54 25.753,60.165 25.753,59.79 25.678,59.79 16.853,59.79 16.853,59.765 16.853,58.14 16.878,58.14 19.378,58.14 19.378,56.99 19.778,56.99
GND on L3 "GND_L03_P024" (solid, remove dead copper, pour order 24): -3.669,56.996 70.901,56.996 70.901,-6.564 -6.499,-6.564 -6.499,-6.244 -6.499,56.972 -3.119,56.972
GND on L4 "GND_L04_P026" (solid, remove dead copper, pour order 26): -0.335,57 74.235,57 74.235,-6.56 -3.165,-6.56 -3.165,-6.24 -3.165,56.976 0.215,56.976
GND on L2 "GND_L02_P030" (solid, remove dead copper, pour order 30): -6.415,57.046 18.212,56.995 18.212,53.665 21.898,53.665 22.415,50.158 22.415,47.521 23.326,47.509 23.326,50.033 38.631,50.033 41.445,52.848 41.427,56.948 69.89,56.97 69.89,-6.59 -7.51,-6.59 -7.51,-6.27 -7.51,56.946 -4.13,56.946

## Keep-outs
L1:
  rectangle: 36.415,50.969 36.726,51.481
  rectangle: 30.607,53.527 30.914,54.033
  rectangle: 29.381,53.544 29.673,54.033
  rectangle: 21.046,55.917 21.357,56.421
Keep-Out Layer:
  lines w0.1: 0,4 0,57 ; 0,56.856 0,62.75 1.726,64.476 26.872,64.476 28.396,62.952 28.396,59.142 30.538,57 30.58,57 67.876,57 70,54.876 70,4 ; 2,2 11.5,2 13.514,-0.014 45.186,-0.014 47.2,2 48.5,2 68,2 ; 3.18,2.102 7.773,2.102 7.773,3.169 3.18,3.169 3.18,2.102
  lines w0.127: 0,4 ccw(c2,4) 2,2 ; 68,2 ccw(c68,4) 70,4

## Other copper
L1:
  text "L1" at 3.506,2.383 h0.51
L2:
  text "L2" at 4.515,2.392 h0.51
L3:
  text "L3" at 5.662,2.373 h0.51
L4:
  text "L4" at 6.783,2.392 h0.51

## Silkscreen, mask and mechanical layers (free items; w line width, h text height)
Top Overlay:
  rectangle: 56.232,52.004 58.289,52.708
  lines w0.1: 0.26,57.01 30.333,57.01
  lines w0.2: 19.857,45.441 20.342,45.441 ; 19.867,47.465 20.352,47.465 ; 19.917,41.445 20.402,41.445 ; 20.17,43.44 20.317,43.44 ; 22.817,5.955 19.006,5.955 19.006,26.577 22.817,26.577 ; 22.842,39.295 22.842,39.78 ; 23.242,48.758 23.242,49.002 ; 24.83,39.281 24.83,39.766 ; 25.232,48.792 25.232,49.012 ; 26.846,39.458 26.846,39.773 ; 27.241,48.792 27.241,49.277 ; 28.217,5.955 29.816,5.955 29.816,14.35 28.323,14.35 ; 28.23,11.015 28.23,10.998 29.745,10.998 ; 29.254,46.663 29.739,46.663 ; 29.259,44.65 29.708,44.65 ; 29.279,42.668 29.746,42.668 ; 29.766,31.111 29.766,35.052 35.1,35.052 35.1,31.111 ; 29.769,32.395 35.082,32.395 ; 37.461,11.112 37.461,8.662 42.795,8.662 42.795,11.112 ; 40.775,48.935 40.775,50.685 ; 51.262,48.935 51.262,50.728 ; 51.262,50.728 51.262,51.741 40.775,51.741 40.775,50.728 51.262,50.728 ; 14.829,35.752 31.829,35.752 31.829,52.752 14.829,52.752 14.829,35.752
  text "GND" at 5.21,56.314 h0.51
  text "GND" at 2.66,56.274 h0.51
  text "GND" at 63.63,55.984 h0.51
  text "GND" at 66.32,55.944 h0.51
  text "STLINK (Reserved)" at 47.662,55.576 h0.75
  text "VDD" at 14.403,52.987 h0.51 r90
  text "Vref" at 58.98,52.094 h0.51
  text "NRST" at 48.81,52.074 h0.51
  text "SWCLK" at 53.71,52.074 h0.51
  text "SWDIO" at 51.18,52.064 h0.51
  text "GND" at 46.36,52.014 h0.51
  text "2" at 68.575,50.693 h0.51
  text "1" at 1.245,50.595 h0.51
  text "1" at 62.265,50.597 h0.51
  text "5V sources" at 40.574,50.569 h0.6
  text "VDDRF" at 14.453,49.134 h0.51 r90
  text "5V / VIN" at 45.447,49.093 h0.51 r90
  text "USB / STL" at 50.545,49.115 h0.51 r90
  text "USB / MCU" at 47.965,49.085 h0.51 r90
  text "5V / EXT" at 42.988,49.059 h0.51 r90
  text "D15" at 57.412,48.959 h1 r90
  text "3" at 1.135,48.102 h0.51
  text "4" at 68.575,48.052 h0.51
  text "3" at 62.239,47.85 h0.51
  text "VDD" at 40.002,47.07 h0.51 r90
  text "D14" at 57.462,45.983 h1 r90
  text "VDDSMPS" at 14.396,45.488 h0.51 r90
  text "6" at 68.575,45.435 h0.51
  text "5" at 1.135,45.41 h0.51
  text "5" at 62.239,45.158 h0.51
  text "3V3" at 40.117,44.086 h0.51 r90
  text "AVDD" at 61.85,42.934 h1 r90
  text "8" at 68.575,42.921 h0.51
  text "7" at 1.135,42.768 h0.51
  text "7" at 62.239,42.516 h0.51
  text "8" at 7.474,42.223 h0.51
  text "VDD" at 14.376,42.21 h0.51 r90
  text "GND" at 54.936,41.569 h1
  text "10" at 68.575,40.406 h0.51
  text "9" at 1.159,40.381 h0.51
  text "10" at 7.503,40.33 h0.51
  text "9" at 62.263,40.129 h0.51
  text "D13" at 55.1,39.034 h1
  text "12" at 68.575,37.866 h0.51
  text "11" at 0.98,37.79 h0.51
  text "12" at 7.56,37.805 h0.51
  text "11" at 62.084,37.538 h0.51
  text "D12" at 55.219,36.95 h1
  text "IOREF" at 13.661,36.729 h1 r90
  text "RF Part" at 15.254,36.096 h1
  text "14" at 7.445,35.31 h0.51
  text "13" at 0.762,35.25 h0.51
  text "14" at 68.575,35.25 h0.51
  text "13" at 61.866,34.998 h0.51
  text "NRST" at 12.586,34.417 h1
  text "D11" at 55.421,33.386 h1
  text "16" at 7.445,32.814 h0.51
  text "15" at 0.762,32.786 h0.51
  text "16" at 68.575,32.71 h0.51
  text "15" at 61.866,32.534 h0.51
  text "Ext Battery" at 29.73,32.382 h0.75
  text "3V3" at 13.554,31.563 h1 r90
  text "+" at 33.398,31.366 h1
  text "D10" at 55.127,31.378 h1
  text "-" at 30.692,31.311 h1
  text "18" at 68.575,30.195 h0.51
  text "18" at 7.416,30.176 h0.51
  text "17" at 0.762,30.145 h0.51
  text "17" at 61.866,29.893 h0.51
  text "5V" at 13.59,29.425 h1 r90
  text "D9" at 55.85,28.862 h1
  text "20" at 68.575,27.909 h0.51
  text "20" at 7.474,27.766 h0.51
  text "19" at 0.786,27.706 h0.51
  text "VDD" at 22.507,27.555 h0.51
  text "VDD_MCU" at 25.035,27.518 h0.51
  text "19" at 61.89,27.454 h0.51
  text "GND" at 12.576,27.108 h1
  text "D8" at 55.876,26.346 h1
  text "22" at 7.52,25.275 h0.51
  text "22" at 68.575,25.268 h0.51
  text "21" at 0.9,25.166 h0.51
  text "21" at 61.74,25.12 h0.51
  text "GND" at 20.597,24.777 h0.75
  text "GND" at 12.524,24.708 h1
  text "24" at 68.575,22.601 h0.51
  text "24" at 7.531,22.574 h0.51
  text "23" at 0.682,22.525 h0.51
  text "23" at 61.522,22.479 h0.51
  text "D7" at 55.87,22.264 h1
  text "NRST" at 20.024,22.2 h0.75
  text "VIN" at 12.576,21.996 h1
  text "25" at 0.682,20.086 h0.51
  text "25" at 61.522,20.04 h0.51
  text "26" at 68.575,19.985 h0.51
  text "26" at 7.531,19.964 h0.51
  text "D6" at 55.9,19.784 h1
  text "SWDIO" at 19.642,19.719 h0.75
  text "27" at 0.682,17.648 h0.51
  text "27" at 61.522,17.602 h0.51
  text "28" at 68.575,17.597 h0.51
  text "28" at 7.56,17.497 h0.51
  text "A0" at 12.682,17.192 h1
  text "D5" at 55.85,17.164 h1
  text "SWCLK" at 19.261,17.081 h0.75
  text "30" at 7.503,15.117 h0.51
  text "30" at 68.575,15.032 h0.51
  text "29" at 0.706,14.93 h0.51
  text "29" at 61.546,14.884 h0.51
  text "A1" at 12.763,14.688 h1
  text "SWO" at 20.342,14.661 h0.75
  text "D4" at 55.894,14.666 h1
  text "MB1355D" at 18.243,12.507 h2.5 r90
  text "32" at 7.531,12.478 h0.51
  text "32" at 68.575,12.466 h0.51
  text "31" at 0.9,12.415 h0.51
  text "31" at 61.74,12.369 h0.51
  text "A2" at 12.743,12.293 h1
  text "D3" at 55.829,12.139 h1
  text "VDD / MCU" at 20.215,11.321 h0.75
  text "T_VDD" at 29.923,10.935 h0.6 r90
  text "TX" at 38.208,10.074 h0.75
  text "RX" at 40.891,10.039 h0.75
  text "34" at 7.531,9.982 h0.51
  text "34" at 68.575,9.926 h0.51
  text "33" at 0.682,9.901 h0.51
  text "33" at 61.522,9.855 h0.51
  text "A3" at 12.682,9.681 h1
  text "D2" at 55.76,9.574 h1
  text "TX" at 21.233,9.413 h0.75
  text "RX" at 29.423,9.22 h0.75 r90
  text "L" at 31.57,9.122 h7.62
  text "STLINK" at 37.537,8.803 h0.75
  text "36" at 68.575,7.412 h0.51
  text "36" at 7.56,7.372 h0.51
  text "35" at 0.682,7.285 h0.51
  text "35" at 61.522,7.239 h0.51
  text "D1" at 55.916,7.194 h1
  text "A4" at 12.682,7.177 h1
  text "RX" at 21.265,6.836 h0.75
  text "TX" at 29.423,6.688 h0.75 r90
  text "Reset" at 38.643,5.595 h1
  text "38" at 7.488,4.745 h0.51
  text "38" at 68.575,4.745 h0.51
  text "37" at 0.682,4.719 h0.51
  text "A5" at 12.682,4.673 h1
  text "37" at 61.522,4.673 h0.51
  text "D0" at 55.85,4.524 h1
  text "COM" at 44.922,4.058 h0.75 r90
Bottom Overlay:
  rectangle: 57.157,17.252 57.62,18.298
  rectangle: 56.12,17.242 56.588,18.298
  lines w0.1: 29.8,31.116 29.8,28.612 35.074,28.612 35.074,31.142 29.804,31.142 ; 29.916,24.591 29.916,24.533 29.926,24.523 29.979,24.523 30.028,24.474 29.896,24.474 29.852,24.518 29.852,24.515 29.765,24.428 30.103,24.428 30.162,24.369 29.701,24.369 29.645,24.313 30.223,24.313 30.281,24.255 29.599,24.255 29.54,24.196 30.306,24.196 30.381,24.121 29.438,24.121 29.36,24.043 30.484,24.043 30.579,23.948 29.267,23.948 29.339,23.876 29.341,23.876 ; 29.93,20.949 29.93,21.008 29.92,21.018 29.867,21.018 29.818,21.066 29.95,21.066 29.994,21.023 29.994,21.025 30.081,21.113 29.743,21.113 29.684,21.171 30.145,21.171 30.201,21.227 29.623,21.227 29.565,21.286 30.247,21.286 30.306,21.344 29.54,21.344 29.465,21.42 30.408,21.42 30.486,21.498 29.362,21.498 29.267,21.593 30.579,21.593 30.507,21.664 30.505,21.664 ; 32.426,26.536 28.545,26.536 28.545,18.986 32.523,18.986 ; 34.201,38.893 34.662,36.546 34.783,36.485 ; 36.36,35.169 36.718,35.236 36.875,38.083 ; 29.341,23.876 30.7,23.876 29.923,24.652 29.147,23.876 29.341,23.876 ; 30.505,21.664 29.146,21.664 29.923,20.888 30.699,21.664 30.505,21.664 ; 7.089,42.816 7.424,42.816 10.913,42.816 10.913,55.856 7.424,55.856 7.089,55.856 7.089,42.816
  text "L" at 5.25,59.826 h7.62
  text "GND" at 3.805,55.824 h0.51
  text "GND" at 6.447,55.824 h0.51
  text "GND" at 67.331,55.316 h0.51
  text "GND" at 64.715,55.278 h0.51
  text "GND" at 10.186,54.222 h0.55 r270
  text "2" at 6.696,51.636 h0.51
  text "AT3" at 10.196,51.611 h0.55 r270
  text "2" at 68.607,50.719 h0.51
  text "1" at 1.595,50.515 h0.51
  text "1" at 62.648,50.388 h0.51
  text "4" at 6.696,49.031 h0.51
  text "AT2" at 10.196,48.968 h0.55 r270
  text "4" at 68.631,48.077 h0.51
  text "3" at 1.713,47.975 h0.51
  text "3" at 62.648,47.848 h0.51
  text "AT1" at 10.204,46.498 h0.55 r270
  text "6" at 6.752,46.425 h0.51
  text "6" at 68.583,45.461 h0.51
  text "5" at 1.713,45.435 h0.51
  text "5" at 62.648,45.308 h0.51
  text "I" at 28.37,44.437 h7.62
  text "8" at 6.752,44.044 h0.51
  text "AT0" at 10.229,43.782 h0.55 r270
  text "8" at 68.607,42.946 h0.51
  text "7" at 1.713,42.895 h0.51
  text "7" at 62.648,42.768 h0.51
  text "Analog Test Pin (Reserved)" at 5.761,41.803 h0.6 r270
  text "C" at 24.742,40.567 h7.62
  text "10" at 68.979,40.432 h0.51
  text "9" at 1.713,40.355 h0.51
  text "10" at 7.943,40.279 h0.51
  text "9" at 62.648,40.228 h0.51
  text "12" at 68.979,37.892 h0.51
  text "11" at 1.713,37.815 h0.51
  text "12" at 7.943,37.739 h0.51
  text "11" at 62.648,37.688 h0.51
  text "CR2032" at 48.659,36.164 h0.9 r270
  text "13" at 1.713,35.275 h0.51
  text "14" at 69.003,35.275 h0.51
  text "13" at 62.648,35.148 h0.51
  text "14" at 7.967,35.123 h0.51
  text "15" at 1.713,32.735 h0.51
  text "16" at 68.955,32.735 h0.51
  text "15" at 62.648,32.608 h0.51
  text "16" at 7.919,32.583 h0.51
  text "+" at 35.767,31.841 h1 r180
  text "-" at 30.19,31.808 h1 r180
  text "18" at 68.979,30.221 h0.51
  text "17" at 1.713,30.195 h0.51
  text "18" at 7.943,30.068 h0.51
  text "17" at 62.648,30.068 h0.51
  text "CN4" at 28.28,28.483 h1 r270
  text "20" at 69.059,27.935 h0.51
  text "20" at 8.023,27.782 h0.51
  text "19" at 1.713,27.655 h0.51
  text "19" at 62.648,27.528 h0.51
  text "Ext Battery" at 35.922,26.327 h0.75
  text "22" at 69.059,25.293 h0.51
  text "22" at 8.023,25.141 h0.51
  text "21" at 1.713,25.115 h0.51
  text "21" at 62.648,24.988 h0.51
  text "Bat" at 32.304,24.924 h1
  text "24" at 69.083,22.626 h0.51
  text "23" at 1.713,22.575 h0.51
  text "24" at 8.047,22.474 h0.51
  text "23" at 62.648,22.448 h0.51
  text "25" at 1.713,20.035 h0.51
  text "26" at 69.035,20.01 h0.51
  text "25" at 62.648,19.908 h0.51
  text "26" at 7.999,19.858 h0.51
  text "ExtS" at 32.271,19.516 h1
  text "28" at 69.059,17.622 h0.51
  text "27" at 1.713,17.495 h0.51
  text "28" at 8.023,17.47 h0.51
  text "27" at 62.648,17.368 h0.51
  text "30" at 69.059,15.057 h0.51
  text "29" at 1.713,14.955 h0.51
  text "30" at 8.023,14.905 h0.51
  text "29" at 62.648,14.828 h0.51
  text "32" at 69.059,12.492 h0.51
  text "31" at 1.713,12.415 h0.51
  text "32" at 8.023,12.339 h0.51
  text "31" at 62.648,12.288 h0.51
  text "34" at 69.083,9.952 h0.51
  text "33" at 1.713,9.875 h0.51
  text "34" at 8.047,9.799 h0.51
  text "33" at 62.648,9.748 h0.51
  text "36" at 69.035,7.437 h0.51
  text "35" at 1.713,7.335 h0.51
  text "36" at 7.999,7.285 h0.51
  text "35" at 62.648,7.208 h0.51
  text "H" at 35.357,6.095 h7.62
  text "37" at 1.713,4.795 h0.51
  text "38" at 69.059,4.77 h0.51
  text "37" at 62.648,4.668 h0.51
  text "38" at 8.023,4.618 h0.51
  text "ST-LINK" at 47.609,2.936 h1 r270
  text "USB_USER" at 44.75,1.794 h1 r270
Mechanical 1:
  lines w0.1: 0,4 0,57 0,62.75 1.726,64.476 26.872,64.476 28.396,62.952 28.396,59.142 30.538,57 32.714,57 67.876,57 70,54.876 70,4 ; 2,2 11.37,2 11.5,2 13.501,-0.001 45.173,-0.001 47.164,1.989 ; 47.2,2 68,2
  lines w0.127: 0,4 ccw(c2,4) 2,2 ; 68,2 ccw(c68,4) 70,4
Mechanical 2:
  lines w0.1: 0,4 ccw(c2,4) 2,2 11.5,2 13.514,-0.014 45.186,-0.014 47.2,2 68,2 ccw(c68,4) 70,4 70,54.876 67.876,57 30.538,57 28.396,59.142 28.396,62.952 26.872,64.476 1.726,64.476 0,62.75 0,4
Mechanical:
  lines w0.1: -3.203,5.04 66.75,5.04 ; -1.991,0 13.5,0 ; 0,-3.336 0,4 ; 0,62.75 0,73.736 ; 3.25,-8.752 3.25,5.04 ; 5.79,-8.857 5.79,5.04 ; 26.872,64.476 79.068,64.476 ; 28.396,62.952 28.396,68.367 ; 45.2,-0.014 79.374,-0.014 ; 46.98,54.245 46.98,61.319 ; 46.98,63 46.98,54.204 87.224,54.204 ; 49.52,54.204 49.52,63 ; 59.68,54.204 59.68,63.443 ; 64.21,-8.708 64.21,5.04 ; 66.75,-13.228 66.75,5.04 ; 66.75,50.76 66.75,70.457 ; 66.812,50.76 87.177,50.76 ; 66.972,1.992 85.981,1.992 ; 67.876,57 83.142,57 ; 70,-13.324 70,4.566 ; 70,54.876 70,73.145 ; 85.836,5.04 66.75,5.04
  lines w0.254: 0,67.306 0,67.814 ; 0,70.68 0,71.188 ; 0.71,-7.539 3.25,-7.539 ; 1.524,67.052 0,67.56 ; 1.524,68.068 0,67.56 ; 1.524,70.426 0,70.934 ; 1.524,71.442 0,70.934 ; 1.726,-8.047 3.25,-7.539 ; 1.726,-7.031 3.25,-7.539 ; 3.25,-7.793 3.25,-7.285 ; 3.25,-4.742 3.25,-4.234 ; 4.774,-4.996 3.25,-4.488 ; 4.774,-3.98 3.25,-4.488 ; 5.79,-7.793 5.79,-7.285 ; 7.314,-8.047 5.79,-7.539 ; 7.314,-7.031 5.79,-7.539 ; 8.078,67.56 0,67.56 ; 8.33,-7.539 5.79,-7.539 ; 20.318,67.56 28.396,67.56 ; 26.872,67.052 28.396,67.56 ; 26.872,68.068 28.396,67.56 ; 28.396,67.306 28.396,67.814 ; 30.404,-4.485 3.25,-4.488 ; 31.801,70.934 0,70.934 ; 38.2,70.934 70,70.934 ; 39.596,-4.484 66.75,-4.481 ; 44.44,61.573 46.98,61.573 ; 45.456,61.065 46.98,61.573 ; 45.456,62.081 46.98,61.573 ; 46.98,61.319 46.98,61.827 ; 49.52,61.319 49.52,61.827 ; 51.044,61.065 49.52,61.573 ; 51.044,62.081 49.52,61.573 ; 52.06,61.573 49.52,61.573 ; 57.14,61.683 59.68,61.683 ; 58.156,61.175 59.68,61.683 ; 58.156,62.191 59.68,61.683 ; 59.68,61.429 59.68,61.937 ; 61.67,-6.001 64.21,-6.001 ; 62.686,-6.509 64.21,-6.001 ; 62.686,-5.493 64.21,-6.001 ; 64.19,68.649 66.73,68.65 ; 64.21,-12.001 66.75,-12.001 ; 64.21,-6.255 64.21,-5.747 ; 65.206,68.141 66.73,68.65 ; 65.206,69.157 66.73,68.65 ; 65.226,-12.509 66.75,-12.001 ; 65.226,-11.493 66.75,-12.001 ; 65.226,-4.989 66.75,-4.481 ; 65.226,-3.973 66.75,-4.481 ; 66.73,68.396 66.73,68.904 ; 66.75,-12.255 66.75,-11.747 ; 66.75,-6.255 66.75,-5.747 ; 66.75,-4.735 66.75,-4.227 ; 66.75,61.429 66.75,61.937 ; 68.274,-6.509 66.75,-6.001 ; 68.274,-5.493 66.75,-6.001 ; 68.274,61.175 66.75,61.683 ; 68.274,62.191 66.75,61.683 ; 68.476,70.426 70,70.934 ; 68.476,71.442 70,70.934 ; 69.29,-6.001 66.75,-6.001 ; 69.29,61.683 66.75,61.683 ; 70,-12.255 70,-11.747 ; 70,68.396 70,68.904 ; 70,70.68 70,71.188 ; 71.524,-12.509 70,-12.001 ; 71.524,-11.493 70,-12.001 ; 71.524,68.142 70,68.65 ; 71.524,69.158 70,68.65 ; 72.54,-12.001 70,-12.001 ; 72.54,68.65 70,68.65 ; 73.723,1.524 74.231,0 ; 73.723,55.476 74.231,57 ; 73.977,0 74.485,0 ; 73.977,57 74.485,57 ; 74.231,25.301 74.231,0 ; 74.231,31.699 74.231,57 ; 74.739,1.524 74.231,0 ; 74.739,55.476 74.231,57 ; 78.084,1.51 78.592,-0.014 ; 78.084,62.952 78.592,64.476 ; 78.338,-0.014 78.846,-0.014 ; 78.338,64.476 78.846,64.476 ; 78.592,26.873 78.592,-0.014 ; 78.592,37.589 78.592,64.476 ; 79.1,1.51 78.592,-0.014 ; 79.1,62.952 78.592,64.476 ; 81.29,52.68 81.798,54.204 ; 81.29,58.524 81.798,57 ; 81.544,54.204 82.052,54.204 ; 81.544,57 82.052,57 ; 81.798,51.664 81.798,54.204 ; 81.798,59.54 81.798,57 ; 82.306,52.68 81.798,54.204 ; 82.306,58.524 81.798,57 ; 86.049,49.236 86.557,50.76 ; 86.049,55.728 86.557,54.204 ; 86.303,50.76 86.811,50.76 ; 86.303,54.204 86.811,54.204 ; 86.557,48.22 86.557,50.76 ; 86.557,56.744 86.557,54.204 ; 87.065,49.236 86.557,50.76 ; 87.065,55.728 86.557,54.204
  text "70mm" at 32.055,70.02 h1.52
  text "28.396mm" at 8.332,66.646 h1.52
  text "3.27mm" at 64.023,64.993 h1.52 r0.01
  text "7.07mm" at 58.873,58.027 h1.52
  text "2.54mm" at 43.908,57.917 h1.52
  text "2.796mm" at 85.455,50.498 h1.52 r90
  text "3.444mm" at 90.214,47.378 h1.52 r90
  text "64.49mm" at 79.506,27.127 h1.52 r90
  text "57mm" at 75.145,25.555 h1.52 r90
  text "63.5mm" at 30.658,-5.399 h1.52 r0.01
  text "2.54mm" at 61.138,-9.658 h1.52
  text "2.54mm" at 0.178,-11.196 h1.52
  text "3.25mm" at 64.033,-15.658 h1.52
